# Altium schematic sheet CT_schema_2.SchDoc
size 461 x 327 mm
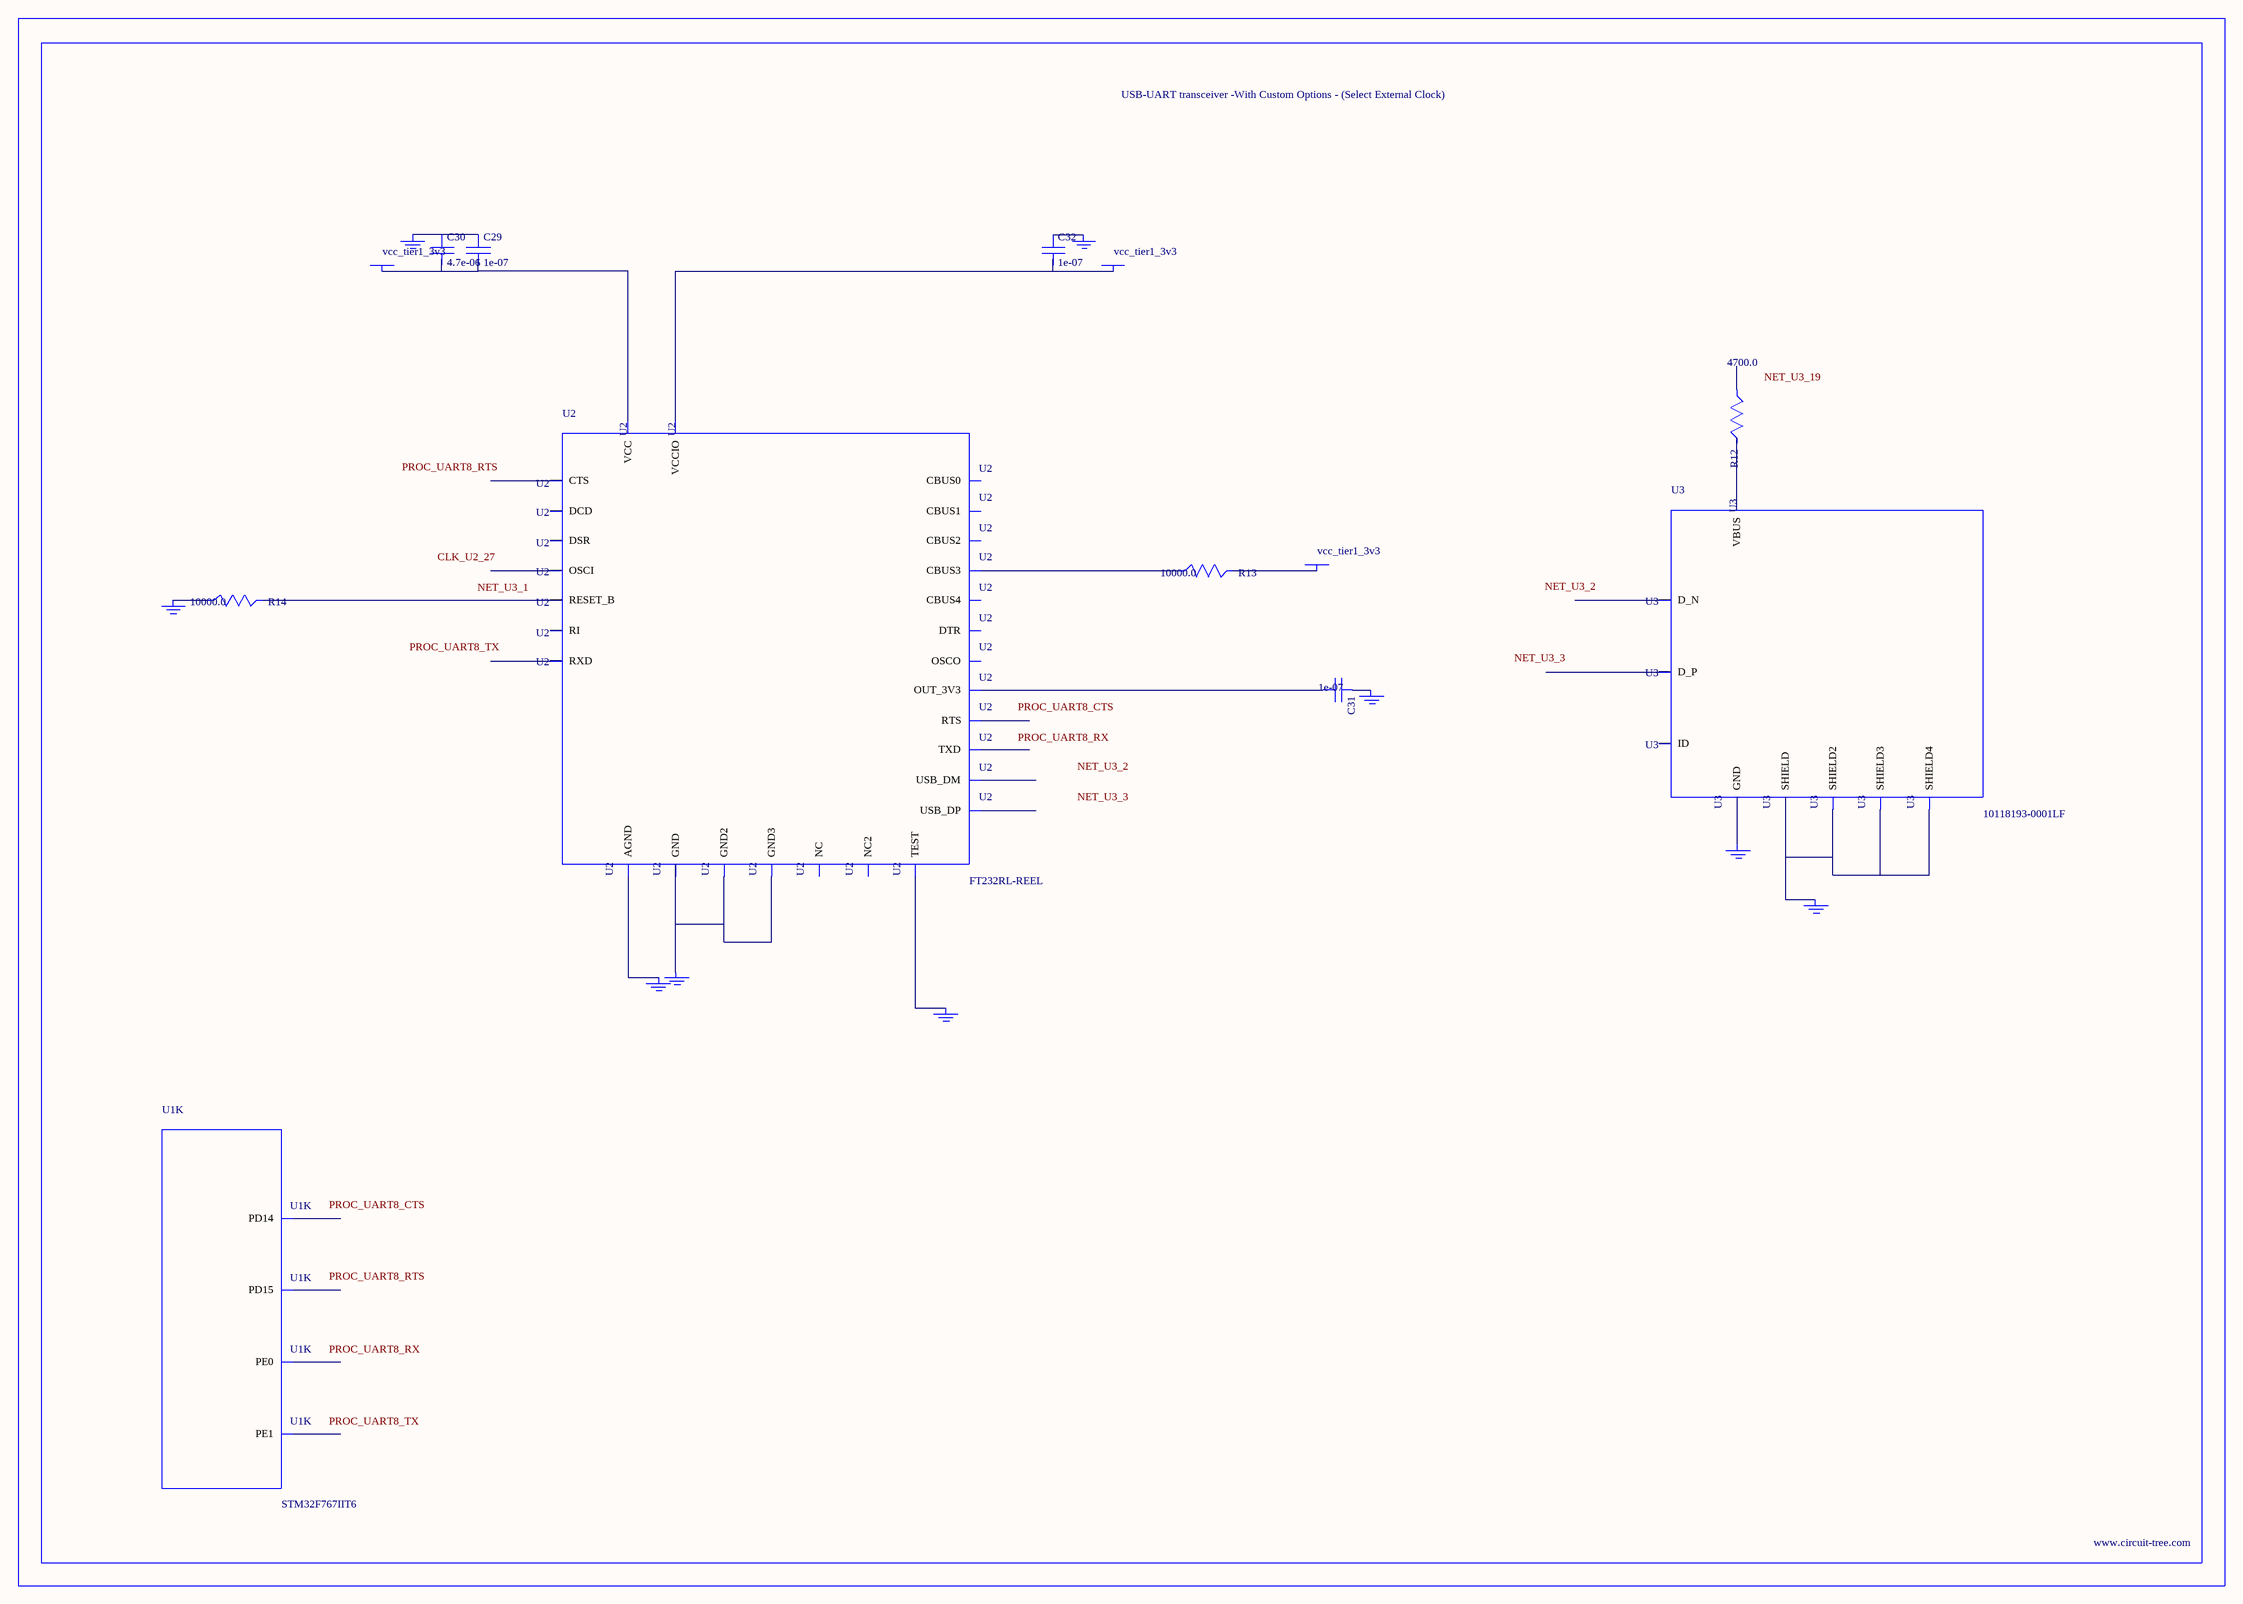
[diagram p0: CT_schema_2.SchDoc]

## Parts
BORDER1  (no value)
C29  1e-07  [C0402]
C30  4.7e-06  [C0805]
C31  1e-07  [C0402]
C32  1e-07  [C0402]
GND_INSTANCE_1_0  (no value)
GND_INSTANCE_1_1  (no value)
GND_INSTANCE_1_2  (no value)
GND_INSTANCE_1_3  (no value)
GND_INSTANCE_1_4  (no value)
GND_INSTANCE_1_5  (no value)
GND_INSTANCE_1_6  (no value)
GND_INSTANCE_1_7  (no value)
GND_INSTANCE_1_8  (no value)
POWER_INSTANCE_1_0  vcc_tier1_3v3
POWER_INSTANCE_1_1  vcc_tier1_3v3
POWER_INSTANCE_1_2  vcc_tier1_3v3
R12  4700.0  [R0603]
R13  10000.0  [R0603]
R14  10000.0  [R0603]
U1  STM32F767IIT6  [LQFP176]  (part K of 15)
U2  FT232RL-REEL  [SSOP-28]
U3  10118193-0001LF  [FCI_10118193-0001LF]

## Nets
NetC29_1: C29.1 C30.1 GND_INSTANCE_1_3.0(GND)
NetC29_2: C29.2 C30.2 POWER_INSTANCE_1_2.0(PWR) U2.20(VCC)
NetC31_1: C31.1 GND_INSTANCE_1_1.0(GND)
NetC31_2: C31.2 U2.17(OUT_3V3)
NetC32_1: C32.1 GND_INSTANCE_1_0.0(GND)
NetC32_2: C32.2 POWER_INSTANCE_1_0.0(PWR) U2.4(VCCIO)
NetGND_INSTANCE_1_2_0: GND_INSTANCE_1_2.0(GND) R14.1
NetGND_INSTANCE_1_4_0: GND_INSTANCE_1_4.0(GND) U2.25(AGND)
NetGND_INSTANCE_1_5_0: GND_INSTANCE_1_5.0(GND) U2.26(TEST)
NetGND_INSTANCE_1_6_0: GND_INSTANCE_1_6.0(GND) U2.7(GND) U2.18(GND2) U2.21(GND3)
NetGND_INSTANCE_1_7_0: GND_INSTANCE_1_7.0(GND) U3.6(SHIELD) U3.7(SHIELD2) U3.8(SHIELD3) U3.9(SHIELD4)
NetGND_INSTANCE_1_8_0: GND_INSTANCE_1_8.0(GND) U3.5(GND)
NetPOWER_INSTANCE_1_1_0: POWER_INSTANCE_1_1.0(PWR) R13.2
NetR12_2: R12.2 U3.1(VBUS)
NetR13_1: R13.1 U2.14(CBUS3)
NetR14_2: R14.2 U2.19(RESET_B)

Not connected (* = marked no-connect by the designer): R12 1; U1 104(PD14) 105(PD15) 169(PE0) 170(PE1); U2 1(TXD) 2(DTR) 3(RTS) 5(RXD) 6(RI) 8(NC) 9(DSR) 10(DCD) 11(CTS) 12(CBUS4) 13(CBUS2) 15(USB_DP) 16(USB_DM) 22(CBUS1) 23(CBUS0) 24(NC2) 27(OSCI) 28(OSCO); U3 2(D_N) 3(D_P) 4(ID)

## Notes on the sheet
- Labels drawn without touching a wire or pin: CLK_U2_27, NET_U3_1, NET_U3_2, NET_U3_3, NET_U3_19, PROC_UART8_CTS, PROC_UART8_RTS, PROC_UART8_RX, PROC_UART8_TX

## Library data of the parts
BORDER1 = BORDER_PAGE1
C29 C31 C32 = C0402C104K3RACTU
C30 = C0805C475K4RACTU
GND_INSTANCE_1_0-GND_INSTANCE_1_8 = GND
POWER_INSTANCE_1_0-POWER_INSTANCE_1_2 = PWR
R12 = RC0603JR-074K7L
R13 R14 = RC0603JR-0710KL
